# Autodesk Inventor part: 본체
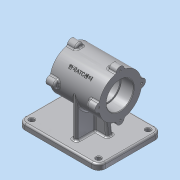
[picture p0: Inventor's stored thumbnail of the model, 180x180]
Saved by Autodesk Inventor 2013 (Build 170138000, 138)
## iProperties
Created: 2015-12
Part Number: 본체
Material: 알루미늄 6061
Document SubType Name: Modeling
Designer: dgall
Density: 2.71 g/cm^3
Mass: 1160.78 g
Surface Area: 819.071 cm^2
Volume: 428.332 cm^3
Author: dgall
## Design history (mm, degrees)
sketch "스케치1"
  geometry: L1 (-70, 55)-(70, 55); L2 (70, 55)-(70, -55); L3 (70, -55)-(-70, -55); L4 (-70, -55)-(-70, 55); 1 further point
  constraints: 8 end point, 2 parallel, 1 horizontal, 1 perpendicular
  dimensions: "d0" = 140 distance of L1.start L1.end; "d2" = 110 distance of L1.end L2.end; "d3" = 70 distance from line of point (0, 0) L4; "d4" = 55 distance from line of point (0, 0) L3
extrude "돌출1" new body sketch "스케치1" distance "d5" = 10; taper "d6" = 0 deg
node "작업 평면1"
sketch "스케치2"
  geometry: L1 (70, 55)-(-70, 55) reference; L2 (-70, 55)-(-70, -55) reference; L3 (-70, -55)-(70, -55) reference; L4 (70, -55)-(70, 55) reference; L5 (-70, 0)-(70, 0); L6 (-32.5, 37)-(52.5, 37); L7 (52.5, 37)-(52.5, 23.5); L8 (52.5, 23.5)-(30.5, 23.5); L9 (30.5, 23.5)-(30.5, 21); L10 (30.5, 21)-(-10.5, 21); L11 (-10.5, 21)-(-10.5, 23.5); L12 (-32.5, 37)-(-32.5, 23.5); L13 (-32.5, 23.5)-(-10.5, 23.5); 1 further point
  constraints: 18 end point, 4 parallel, 4 perpendicular, 2 midpoint
  dimensions: "d8" = 42 diameter of L10 L5; "d9" = 74 diameter of L6 L5; "d11" = 47 diameter of L8 L5; "d12" = 47 diameter of L13 L5; "d13" = 37.5 distance between parallel lines of L2 L12; "d14" = 85 distance between parallel lines of L7 L12; "d15" = 22 distance between parallel lines of L11 L12; "d16" = 41 distance between parallel lines of L9 L11
revolve "회전1" sketch "스케치2" stored, may be unused: angle "d17" = 90 deg
node "작업 평면2"
sketch "스케치3"
  geometry: L1 (-80, -55)-(-80, 55) reference; L2 (-80, -55)-(-70, -55) reference; L3 (-70, 55)-(-70, -55) reference; L4 (-80, 55)-(-70, 55) reference; L5 (0, -37)-(-70, -37); L6 (0, 37)-(-70, 37); C1 r 23.5 at (0, 0) reference; A1 r 37 centre (0, 0) between (0, 37) and (0, -37) reference; 1 further point
  constraints: 4 end point, 2 parallel, 2 point on circle, 2 point on line, 2 tangent
extrude "돌출2" join sketch "스케치3" stored distance "d19" = 8; taper "d20" = 0 deg
sketch "스케치4"
  geometry: L1 (32.5, 43)-(-52.5, 43) reference; L2 (-70, 10)-(70, 10) reference; L3 (10.948, 43)-(15, 10); L4 (-30.948, 43)-(-35, 10); L5 (-14, 10)-(-14, 80) reference; 1 further point
  constraints: 4 end point, 4 point on line
  dimensions: "d21" = 97 deg angle of L2 L3; "d22" = 29 distance from line of L5 L3.end; "d23" = 97 deg angle of L2 L4; "d24" = 50 distance of L3.end L4.end
feature "리브1" dims "d25" = 1, "d26" = 10, "d27" = 0, "d28" = 0, "d29" = 1, "d30" = 1
feature "리브2" dims "d31" = 1, "d32" = 10, "d33" = 0, "d34" = 0, "d35" = 1, "d36" = 1
fillet "모깎기1" dims "d52" = 3
fillet "모깎기2" dims "d53" = 3
fillet "모깎기3" dims "d54" = 3
fillet "모깎기4" dims "d55" = 3
fillet "모깎기5" dims "d56" = 12
fillet "모깎기6" dims "d57" = 3
sketch "스케치7" dims "d66" = 10, "d73" = 10, "d80" = 10
  geometry: L1 (58, -52)-(-58, -52) reference; L2 (67, 43)-(67, -43) reference; L3 (-58, 52)-(58, 52) reference; L4 (58, 55)-(-58, 55) reference; L5 (-70, 43)-(-70, -43) reference; C1 r 4 at (-58, 43); C2 r 4 at (58, 43); C3 r 4 at (58, -43); C4 r 4 at (-58, -43); 1 further point
  constraints: 4 centre point, 2 horizontal, 1 vertical, 6 other
  dimensions: "d58" = 12 distance from line of L4 C1.centre; "d59" = 12 distance from line of L5 C1.centre; "d60" = 8 diameter of C1; "d63" = 116 distance of C1.centre C2.centre; "d70" = 86 distance of C2.centre C3.centre; "d77" = 116 distance of C3.centre C4.centre
extrude "돌출5" cut sketch "스케치7" stored distance "d82" = 15; taper "d83" = 0 deg
chamfer "모따기1" distance "d84" = 1; stored, may be unused: second distance "d85" = 2, angle "d86" = 45 deg
node "작업 평면3"
node "작업 평면5"
sketch "스케치9"
  geometry: L1 (80, 43)-(80, -43) reference; C1 r 7 at (0, 37); 2 further points
  constraints: 1 centre point, 1 vertical alignment, 1 other
  dimensions: "d98" = 14 diameter of C1; "d100" = 80 distance from line of L1 C1.centre
extrude "돌출6" join sketch "스케치9" distance "d101" = 15; taper "d102" = 0 deg
fillet "모깎기7" dims "d103" = 3
sketch "스케치10"
  geometry: L1 (-80, -43)-(-80, 43) reference; C1 r 7 at (0, -37); 2 further points
  constraints: 1 centre point, 1 vertical alignment, 1 other
  dimensions: "d107" = 14 diameter of C1; "d109" = 80 distance from line of L1 C1.centre
extrude "돌출7" join sketch "스케치10" distance "d110" = 15; taper "d111" = 0 deg
fillet "모깎기8" dims "d112" = 3
sketch "스케치11"
  geometry: C1 r 23.5 at (0, -37) reference; C2 r 37 at (0, -37); A1 r 7 centre (0, 0) between (6.889, 1.239) and (-6.889, 1.239) reference; A2 r 7 centre (-37, -37) between (-38.239, -30.111) and (-38.239, -43.889) reference; A3 r 7 centre (0, -74) between (-6.889, -75.239) and (6.889, -75.239) reference; A4 r 7 centre (37, -37) between (38.239, -43.889) and (38.239, -30.111) reference; 1 further point
  constraints: 1 centre point, 1 coincident
  dimensions: "d116" = 74 diameter of C2
hole "구멍1" sketch "스케치11" at (-37, -37), (0, 0), (37, -37), (0, -74) diameter "d118" = 3.242; stored, may be unused: countersink angle "d122" = 90 deg, drill point angle "d124" = 118 deg; dims "d119" = 9, "d120" = 4, "d121" = 2, "d123" = 11
sketch "스케치12"
  geometry: A1 r 7 centre (0, 74) between (6.889, 75.239) and (-6.889, 75.239) reference; A2 r 7 centre (-37, 37) between (-38.239, 43.889) and (-38.239, 30.111) reference; A3 r 7 centre (0, 0) between (-6.889, -1.239) and (6.889, -1.239) reference; A4 r 7 centre (37, 37) between (38.239, 30.111) and (38.239, 43.889) reference; 1 further point
hole "구멍2" sketch "스케치12" at (0, 74), (37, 37), (0, 0), (-37, 37) diameter "d125" = 3.242; stored, may be unused: countersink angle "d129" = 90 deg, drill point angle "d131" = 118 deg; dims "d126" = 9, "d127" = 4, "d128" = 2, "d130" = 11
node "작업 평면6"
node "작업 평면7"
node "작업 평면8"
sketch "스케치14"
  geometry: L1 (-20.739, 3.002)-(20.739, 3.002); L2 (20.739, 3.002)-(20.739, -3.002); L3 (20.739, -3.002)-(-20.739, -3.002); L4 (-20.739, -3.002)-(-20.739, 3.002); L5 (-20.739, 0)-(20.739, 0); L6 (0, 3.002)-(0, -3.002); L7 (42.5, -18.921)-(42.5, 18.921) reference; L8 (-42.5, 37)-(42.5, 37) reference; 1 further point
  constraints: 4 end point, 4 midpoint, 2 other
  dimensions: "d134" = 42.5 distance between parallel lines of L7 L6; "d135" = 37 distance between parallel lines of L8 L5
extrude "돌출8" join sketch "스케치14" stored distance "d136" = 15; taper "d137" = 0 deg
fillet "모깎기9" dims "d138" = 0.3
fillet "모깎기10" dims "d139" = 3
node "솔리드1"
pattern_circular "원형 패턴3" dims angle "d105" = 360 deg
pattern_circular "원형 패턴4" dims angle "d114" = 360 deg
node "투영된 루프1"
node "투영된 루프2"
node "투영된 루프3"
other parameters: "d18" = -42.5, "d87" = -43, "d133" = -0.5
